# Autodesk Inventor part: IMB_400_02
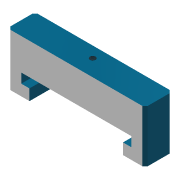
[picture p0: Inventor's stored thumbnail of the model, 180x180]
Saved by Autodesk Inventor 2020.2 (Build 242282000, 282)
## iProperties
Created: 2011-02
Part Number: IMB_400_02
Document SubType Name: Modeling
Designer: F.Stasiak
Density: 2.71 g/cm^3
Material: Aluminium-6061
Mass: 258.209 g
Surface Area: 169.72 cm^2
Volume: 95.28 cm^3
Description: Docisk
Appearance: Ciemnobłękitna
Manager: www.cadconsulting.pl
Company: Fabian Stasiak CAD Consulting
Author: F.Stasiak
Subject: Zbiór ćwiczeń. Autodesk Inventor 2020. Kurs podstawowy
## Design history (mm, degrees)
sketch "Szkic1"
  geometry: L1 (-50, 0)-(50, 0); L2 (50, 0)-(50, -38); L3 (50, -38)-(34, -38); L4 (34, -38)-(34, -30); L5 (34, -30)-(40, -30); L6 (40, -30)-(40, -23); L7 (40, -23)-(-40, -23); L8 (-40, -23)-(-40, -30); L9 (-40, -30)-(-34, -30); L10 (-34, -30)-(-34, -38); L11 (-34, -38)-(-50, -38); L12 (-50, -38)-(-50, 0); L13 (0, 0)-(0, -23); 1 further point
  constraints: 26 end point, 6 perpendicular, 5 parallel, 2 collinear, 2 midpoint, 1 coincident, 1 horizontal, 1 vertical, 1 other
  dimensions: "d0" = 100 distance of L1.start L1.end; "d1" = 8 distance of L9.end L10.end; "d2" = 7 distance of L7.end L8.end; "d4" = 38 distance between parallel lines of L1 L11; "d27" = 80 distance between parallel lines of L6 L8; "d29" = 68 distance between parallel lines of L4 L10
extrude "Wyciągnięcie proste1" new body sketch "Szkic1" distance "d6" = 20; taper "d7" = 0 deg
sketch "Szkic2"
  geometry: L1 (-40, -23)-(40, -23) reference; L2 (0, 0)-(0, -23); 1 further point
  constraints: 2 end point, 2 midpoint
hole "Hole1" sketch "Szkic2" at (0, -11.5) diameter "d11" = 6.5; stored, may be unused: countersink angle "d15" = 90 deg, drill point angle "d17" = 118 deg; dims "d12" = 6, "d13" = 11, "d14" = 5, "d16" = 15
hole "Hole2" diameter "d20" = 4.134; stored, may be unused: countersink angle "d24" = 90 deg, drill point angle "d26" = 118 deg; dims "d18" = 50 (= 0.5 x d0), "d19" = 8, "d21" = 6, "d22" = 15, "d23" = 10, "d25" = 13.5
chamfer "Faza1" distance "d8" = 2; stored, may be unused: second distance "d9" = 2, angle "d10" = 45 deg
node "Bryła1"
